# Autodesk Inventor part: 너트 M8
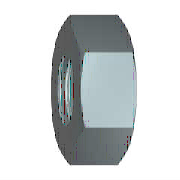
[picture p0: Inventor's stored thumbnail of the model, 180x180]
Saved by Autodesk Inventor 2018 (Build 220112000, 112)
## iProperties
IsCustomPart: 1
Created: 2012-02
Part Number: 너트 M8
Material: 강철, 연강
Description: 6각 너트 및 6각 가는 너트
Document SubType Name: Modeling
Standard: KS B 1012
Designer: mduedu
Standards Organization: KS
Language: ko-KR
Size Designation: M 8
Categories: <MemberInstance><Categories><Category DisplayName="조임쇠" InternalName="e4da775c-781d-43d5-af7c-5136215cf5a6" Mnemonic="FSTN"><Category DisplayName="너트" InternalN
Density: 1 g/cm^3
Appearance: 강철
Author: mduedu
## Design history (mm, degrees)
sketch "스케치1"
  geometry: L1 (-7.506, 0)-(-3.753, 6.5); L2 (-3.753, 6.5)-(3.753, 6.5); L3 (3.753, 6.5)-(7.506, 0); L4 (7.506, 0)-(3.753, -6.5); L5 (3.753, -6.5)-(-3.753, -6.5); L6 (-3.753, -6.5)-(-7.506, 0); 2 further points
  constraints: 12 end point, 1 coincident, 1 horizontal, 11 other
  dimensions: "d0" = 15.01111 distance of L3.end L1.start (= 1.1547 x SW)
extrude "본체" new body sketch "스케치1" distance "d1" = 5 (= KOH); taper "d2" = 0 deg
sketch "스케치2"
  geometry: L1 (0, 3.753)-(0, 7.506) reference; L2 (0, 7.506)-(5, 7.506) reference; L3 (5, 3.753)-(5, 7.506) reference; L4 (-1, 0)-(6, 0) reference; L5 (0.581, 7.506)-(0, 6.5); L6 (4.419, 7.506)-(5, 6.5)
  constraints: 4 end point, 4 point on line
  dimensions: "d3" = 30 deg angle of L1 L5 (= ANG1); "d4" = 30 deg angle of L3 L6 (= ANG2); "d5" = 13 diameter of L5.end L4 (= SW0); "d6" = 13 diameter of L6.end L4 (= SW01)
revolve "모따기1" sketch "스케치2" stored, may be unused: angle "d7" = 90 deg
sketch "스케치3"
  geometry: A1 r 6.5 centre (0, 0) between (-3.25, -5.629) and (3.25, -5.629) reference; 1 further point
  constraints: 1 coincident
hole "스레드" sketch "스케치3" at (0, 0) diameter "d25" = 6.647; stored, may be unused: countersink angle "d29" = 82 deg, drill point angle "d31" = 118 deg; dims "d26" = 6, "d27" = 4, "d28" = 2, "d30" = 8
workaxis "Work Axis1"
workplane "Work Plane1"
body "Solid1"
chamfer "모따기2" distance "d8" = 0.67658 (= -0.5 x GD1 + 0.5 x NND); stored, may be unused: angle "d9" = 30 deg, second distance "d40" = 0.67658 (= -0.5 x GD1 + 0.5 x NND)
chamfer "모따기3" distance "d10" = 0.67658 (= -0.5 x GD1 + 0.5 x NND); stored, may be unused: angle "d11" = 30 deg, second distance "d41" = 0.67658 (= -0.5 x GD1 + 0.5 x NND)
other parameters: "ANG1" = 30 deg [user parameter; used in 1 equation term], "ANG2" = 30 deg [user parameter; used in 1 equation term], "NND" = 8 [user parameter; used in 4 equation terms], "KOH" = 5 [user parameter; used in 1 equation term], "SW" = 13 [user parameter; used in 4 equation terms], "SW0" = 13 (= SW) [user parameter; used in 1 equation term], "SW01" = 13 (= SW) [user parameter; used in 1 equation term], "GD1" = 6.64684 (computed from THREADDIA, PTC, TOA) [user parameter; used in 4 equation terms], "d13" = 0, "d14" = 0, "d39" = 0, "d42" = 0, "GUL" = 0.67658 (= 0.541266 x PTC) [user parameter], "TPU" = 8 (computed from PTC) [user parameter], "THREADDIA" = 8 [user parameter; used in 1 equation term], "TOA" = 30 deg [user parameter; used in 1 equation term], "PTC" = 1.25 [user parameter; used in 4 equation terms], "E0" = 15.015 (= 1.155 x SW) [user parameter], "GAL" = 0.67658 (= 0.541266 x PTC) [user parameter]
